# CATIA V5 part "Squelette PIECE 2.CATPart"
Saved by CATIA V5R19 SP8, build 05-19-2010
Part number: Squelette PIECE 2
Publications: "Droite.1", "Droite.2", "Plan.1", "Plan.3", "Droite.3", "Plan.7", "Plan.9", "Plan.11"
Bounding box of the stored display mesh (mm): x -6 to 0, y -9.5 to 15.5, z -1 to 19
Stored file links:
  C:\Users\ThinkMotion\Desktop\EU_thinkMotion\iao\IAO_MMS_Groupe3\jbuffard\jbuffard\Squelette PIECE 2.CATPart
  C:\Users\ThinkMotion\Desktop\EU_thinkMotion\iao\IAO_MMS_Groupe3\jbuffard\jbuffard\Mecanisme a coulisse a quatre elements de la griffe d'une camera.CATProduct
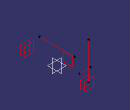
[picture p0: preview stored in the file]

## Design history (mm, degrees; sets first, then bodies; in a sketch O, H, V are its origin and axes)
Set1
  Point1 to Point4: linked copy from another document
  Plane1 to Plane3: linked copy from another document
  Point5: linked copy from another document
  Plane4 to Plane7: linked copy from another document
Set2 "Set géométrique.4"
  Line1: type PtPt, FirstPoint Point1, SecondPoint Point2
  Line2: type PtPt, FirstPoint Point3, SecondPoint Point4
  Plane8: type Offset, RefPlane Plane1, Offset 0
  Plane9: type Offset, RefPlane Plane2, Offset 0
  Line3: type Normal, LineFirstUpto Plane4, LineSecondUpto Plane3, RefPoint Point5, Start 0, End 20
  Plane10: type Offset, RefPlane Plane5, Offset 0
  Plane11: type Offset, RefPlane Plane6, Offset 0
  Plane12: type Offset, RefPlane Plane7, Offset 0
Body1 (main body)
